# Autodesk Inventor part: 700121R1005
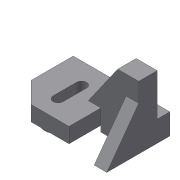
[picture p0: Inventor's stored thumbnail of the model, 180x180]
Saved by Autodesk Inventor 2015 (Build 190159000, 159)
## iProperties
Created: 2020-01
Part Number: 700121R1005
Material: 일반
Document SubType Name: Modeling
Designer: H04
Density: 1 g/cm^3
Appearance: 기본값
Author: H04
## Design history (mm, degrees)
sketch "스케치1"
  geometry: L1 (35, -22)-(-10, -22); L2 (-35, 3)-(-35, 53); L3 (-35, 53)-(80, 53); L4 (80, 53)-(80, 16); L5 (35, -22)-(35, 16); L6 (35, 16)-(80, 16); L7 (80, 16)-(65, 16); L8 (65, 16)-(65, -22); L9 (65, -22)-(80, -22); L10 (80, -22)-(80, 16); L11 (0, 28)-(0, 0); L12 (-6, 28)-(-6, 0); L13 (6, 0)-(6, 28); L14 (-10, -22)-(-35, 3); C1 r 16 at (0, 0); C2 r 10 at (0, 0); A1 r 6 centre (0, 28) between (6, 28) and (-6, 28); A2 r 6 centre (0, 0) between (-6, 0) and (6, 0); 2 further points
  constraints: 30 end point, 5 parallel, 4 centre point, 4 point on circle, 4 tangent, 3 coincident, 2 horizontal, 2 perpendicular, 1 midpoint, 1 vertical
  dimensions: "d0" = 16 radius of C1; "d1" = 10 radius of C2; "d2" = 38 distance between parallel lines of L6 L1; "d3" = 35 distance from line of L2 point (0, 0); "d4" = 53 distance from line of L3 point (0, 0); "d6" = 45 distance of L5.end L4.end; "d7" = 115 distance of L2.end L3.end; "d8" = 38 distance of L1.start L5.end; "d9" = 15 distance of L8.end L9.end; "d10" = 38 distance of L7.end L8.end; "d11" = 6 radius of A1; "d12" = 28 distance of L11.start L11.end; "d13" = 75 distance between parallel lines of L3 L1; "d14" = 25 horizontal distance of L2.start L1.end; "d15" = 45 deg angle of L1 L14
extrude "돌출1" new body sketch "스케치1" distance "d16" = 60; taper "d17" = 0 deg
sketch "스케치2"
  geometry: L1 (0, 0)-(-52.303, 38); L2 (0, 38)-(-60, 38) reference; L3 (-60, 38)-(-60, 0); L4 (-60, 0)-(0, 0); 1 further point
  constraints: 6 end point, 1 perpendicular, 1 point on line, 1 vertical
  dimensions: "d18" = 144 deg angle of L1 L2
extrude "돌출2" cut sketch "스케치2" stored distance "d19" = 60; taper "d20" = 0 deg
extrude "돌출3" join sketch "스케치1" distance "d21" = 25; taper "d22" = 0 deg
sketch "스케치3"
  geometry: L1 (-25, 7)-(45, 7); L2 (45, 7)-(45, 0); L3 (45, 0)-(-25, 0); L4 (-25, 0)-(-25, 7); 2 further points
  constraints: 8 end point, 2 parallel, 1 coincident, 1 horizontal, 1 perpendicular
  dimensions: "d23" = 7 distance of L3.end L1.start; "d24" = 70 distance of L2.end L3.end
extrude "돌출4" cut sketch "스케치3" stored distance "d25" = 25; taper "d26" = 0 deg
extrude "돌출5" join sketch "스케치1" distance "d27" = 7; taper "d28" = 0 deg
sketch "스케치4"
  geometry: L1 (-6, 28)-(-6, 0) reference; L2 (6, 0)-(6, 28) reference; A1 r 6 centre (0, 28) between (6, 28) and (-6, 28) reference; A2 r 6 centre (0, 0) between (-6, 0) and (6, 0) reference; 1 further point
extrude "돌출6" cut sketch "스케치4" distance "d29" = 12; taper "d30" = 0 deg
sketch "스케치5"
  geometry: L1 (45, 0)-(45, 50); L2 (45, 50)-(20, 50); L3 (20, 50)-(-15.01, 0); L4 (-15.01, 0)-(45, 0); 2 further points
  constraints: 8 end point, 2 horizontal, 1 coincident, 1 vertical
  dimensions: "d31" = 25 distance of L1.end L2.end; "d32" = 55 deg angle of L3 L2; "d33" = 50 distance between parallel lines of L4 L2
extrude "돌출7" join sketch "스케치5" distance "d34" = 22; taper "d35" = 0 deg
node "솔리드1"
